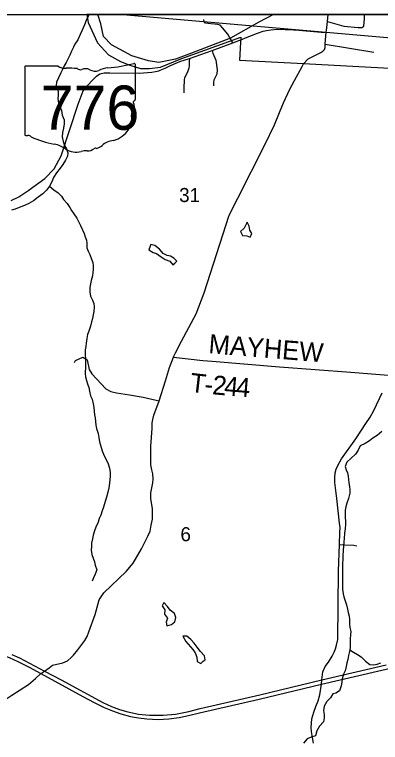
# Model space of a CAD drawing. Extents: x 0 to 34, y 0 to 22.
# Drawn here: x 4.921 to 6.01, y 18.731 to 20.9 of the extents above; entities that cross this region are included whole.
import ezdxf

# ---------------------------------------------------------------- set-up
doc = ezdxf.new("R2010")
doc.units = 0
for name, color, linetype in [('GM_X_City_Street', 7, 'Continuous'), ('GM_X_Corporation', 7, 'Continuous'), ('GM_X_County_Road', 7, 'Continuous'), ('GM_X_Minor_Lake', 7, 'Continuous'), ('GM_X_Minor_River', 7, 'Continuous'), ('GM_X_Rail_Line', 7, 'Continuous'), ('GM_X_Section_Text', 7, 'Continuous'), ('GM_X_State_Location', 7, 'Continuous'), ('GM_X_State_Route', 7, 'Continuous'), ('GM_X_State_Shield', 7, 'Continuous'), ('GM_X_Township_Road', 7, 'Continuous'), ('GM_X_Township_Road_Text', 7, 'Continuous'), ('SH_Data', 7, 'Continuous')]:
    doc.layers.add(name, color=color, linetype=linetype)

msp = doc.modelspace()

# ---------------------------------------------------------------- linework, layer by layer
at = {"layer": 'GM_X_City_Street'}
msp.add_line((5.8464, 20.8121), (5.9912, 20.7882), dxfattribs=at)
for points in [[(5.8528, 20.8797), (5.9019, 20.8656), (5.9446, 20.8613), (5.9548, 20.8618), (5.9608, 20.8657), (5.9629, 20.887), (5.9628, 20.9)], [(5.7819, 20.7534), (5.7957, 20.768), (5.8055, 20.7728), (5.8332, 20.7865), (5.8393, 20.7908), (5.844, 20.7958), (5.8459, 20.8019), (5.8464, 20.8121), (5.8489, 20.8485)]]:
    msp.add_lwpolyline(points, dxfattribs=at)
at = {"layer": 'GM_X_Corporation'}
msp.add_lwpolyline([(7.5423, 20.9), (5.1364, 20.9), (5.1405, 20.8766), (5.1679, 20.8155), (5.2007, 20.7795), (5.2364, 20.7605), (5.2645, 20.749), (5.2964, 20.7394), (5.3232, 20.7393), (5.3551, 20.743), (5.4166, 20.7679), (5.5947, 20.8322), (5.5945, 20.828), (5.5938, 20.8164), (5.5907, 20.7644), (5.7817, 20.7539), (6.0926, 20.7368)], dxfattribs=at)
msp.add_lwpolyline([(6.106, 20.9), (5.2435, 20.9), (6.1004, 20.8259)], close=True, dxfattribs=at)
at = {"layer": 'GM_X_County_Road'}
msp.add_line((5.3944, 19.8788), (5.3957, 19.8816), dxfattribs=at)
for points in [[(5.5856, 20.3524), (5.6666, 20.5116), (5.6951, 20.5713), (5.7096, 20.608), (5.7223, 20.6371), (5.7408, 20.6777), (5.7545, 20.7033), (5.7777, 20.7456), (5.7819, 20.7534)], [(5.3957, 19.8816), (5.4002, 19.8918), (5.4184, 19.9266), (5.4617, 20.0082), (5.4854, 20.0709), (5.5601, 20.3017), (5.5606, 20.3034), (5.5692, 20.32), (5.5856, 20.3524)], [(5.3517, 19.7484), (5.3707, 19.8081), (5.3823, 19.8481), (5.3944, 19.8788)], [(5.0961, 18.9912), (5.1091, 19.0064), (5.1299, 19.0341), (5.1368, 19.046), (5.1423, 19.06), (5.1609, 19.1124), (5.1726, 19.156), (5.1873, 19.1764), (5.2531, 19.2403), (5.2694, 19.259), (5.2739, 19.2654), (5.2988, 19.3072), (5.3181, 19.3452), (5.3245, 19.36), (5.328, 19.3784), (5.3317, 19.396), (5.332, 19.408), (5.332, 19.4279), (5.3272, 19.4563), (5.3263, 19.4743), (5.3325, 19.5045), (5.3333, 19.5161), (5.3323, 19.5308), (5.3301, 19.5435), (5.3269, 19.5579), (5.3272, 19.6132), (5.3304, 19.6663), (5.3311, 19.6829), (5.3328, 19.6935), (5.3359, 19.7063), (5.3517, 19.7484)], [(4.8859, 18.8538), (4.9128, 18.8714), (4.9622, 18.9033), (4.9832, 18.9211), (4.9995, 18.9357), (5.0016, 18.9373), (5.0071, 18.9412), (5.0101, 18.9434), (5.0236, 18.9534), (5.0339, 18.9609), (5.0645, 18.9678), (5.0789, 18.9741), (5.0897, 18.9836), (5.0961, 18.9912)]]:
    msp.add_lwpolyline(points, dxfattribs=at)
at = {"layer": 'GM_X_Minor_Lake'}
for points in [[(5.614, 20.2811), (5.6049, 20.2637), (5.5939, 20.2539), (5.6, 20.2413), (5.6124, 20.2402), (5.623, 20.2364), (5.6254, 20.2424)], [(5.6254, 20.2424), (5.6276, 20.2478), (5.6219, 20.2576), (5.6193, 20.2698), (5.614, 20.2811)], [(5.3215, 20.2022), (5.3207, 20.1988), (5.3339, 20.1912), (5.3438, 20.1882), (5.3577, 20.1779), (5.3698, 20.1696), (5.3835, 20.165), (5.3925, 20.154), (5.3986, 20.1595)], [(5.3986, 20.1595), (5.4043, 20.1646), (5.3956, 20.1741), (5.385, 20.1802), (5.3752, 20.1821), (5.3638, 20.1874), (5.3521, 20.2007), (5.3389, 20.2113), (5.3271, 20.2151), (5.3215, 20.2022)], [(5.3766, 19.1355), (5.3753, 19.137), (5.3655, 19.1477), (5.3602, 19.1378), (5.3681, 19.126), (5.3677, 19.1132), (5.3768, 19.1014), (5.3722, 19.0889), (5.3748, 19.0786), (5.3881, 19.082)], [(5.3881, 19.082), (5.3987, 19.0904), (5.4017, 19.1029), (5.3968, 19.115), (5.3847, 19.1253), (5.3766, 19.1355)], [(5.4217, 19.0475), (5.4312, 19.0312), (5.4516, 19.0076), (5.4587, 18.9974), (5.4633, 18.9845), (5.4644, 18.9716), (5.4753, 18.9663), (5.4829, 18.9725)], [(5.4829, 18.9725), (5.4882, 18.9769), (5.4867, 18.9883), (5.4746, 19.0012), (5.4648, 19.0141), (5.4557, 19.0262), (5.4455, 19.0376), (5.4338, 19.0471), (5.4217, 19.0475)]]:
    msp.add_lwpolyline(points, dxfattribs=at)
at = {"layer": 'GM_X_Minor_River'}
for points in [[(5.1425, 20.9), (5.1401, 20.8954), (5.134, 20.8822), (5.1297, 20.8689), (5.1228, 20.8534), (5.1163, 20.8409), (5.1094, 20.8251), (5.1006, 20.8122), (5.0963, 20.8024), (5.0906, 20.7907), (5.0856, 20.7793), (5.0806, 20.7695), (5.0749, 20.757), (5.0691, 20.7472), (5.0634, 20.7363), (5.0584, 20.726), (5.0515, 20.7117), (5.0457, 20.6981), (5.0445, 20.6886), (5.0486, 20.6787), (5.0504, 20.6692), (5.0507, 20.659), (5.0503, 20.6495), (5.0521, 20.6358), (5.0554, 20.626), (5.061, 20.6142), (5.0632, 20.5997), (5.0688, 20.5864), (5.0687, 20.5743), (5.0667, 20.5614), (5.064, 20.5489), (5.0631, 20.5356), (5.0653, 20.522), (5.0701, 20.5098), (5.0761, 20.4999), (5.0798, 20.4874), (5.0782, 20.4775), (5.0729, 20.4658), (5.0648, 20.453), (5.0572, 20.4424), (5.0461, 20.4284), (5.0373, 20.4148), (5.0323, 20.4012), (5.0247, 20.3888), (5.0163, 20.3771), (5.0056, 20.3661), (4.9915, 20.356), (4.9774, 20.3447), (4.9634, 20.3364), (4.9505, 20.3305), (4.9349, 20.3253), (4.9224, 20.3204), (4.9122, 20.3167)], [(5.0247, 20.3888), (5.0378, 20.3777), (5.0506, 20.3685), (5.0604, 20.3586), (5.0671, 20.3487), (5.0773, 20.3368), (5.0851, 20.3254), (5.0908, 20.3159), (5.0975, 20.3056), (5.1061, 20.2934), (5.1117, 20.2831), (5.1177, 20.271), (5.1278, 20.247), (5.1315, 20.2371), (5.1352, 20.2272), (5.1359, 20.2174), (5.1365, 20.2048), (5.1406, 20.1946), (5.1447, 20.1847), (5.1499, 20.1706), (5.1537, 20.1611), (5.1555, 20.1512), (5.155, 20.1406), (5.1542, 20.1312), (5.1526, 20.1213), (5.1495, 20.1077), (5.1468, 20.0974), (5.1448, 20.0861), (5.1447, 20.074), (5.1469, 20.061), (5.1529, 20.0485), (5.157, 20.0386), (5.1577, 20.0291), (5.1568, 20.0151), (5.1549, 20.0052), (5.1529, 19.9946), (5.1502, 19.984), (5.1474, 19.9715), (5.142, 19.956), (5.1386, 19.9462), (5.1362, 19.9348), (5.1342, 19.9208), (5.133, 19.9102), (5.1314, 19.9007), (5.131, 19.8867), (5.132, 19.873), (5.1323, 19.8617), (5.1319, 19.8507), (5.131, 19.8302), (5.132, 19.8207), (5.1354, 19.8097), (5.1383, 19.7998), (5.1424, 19.788), (5.1442, 19.7778), (5.1472, 19.7633), (5.1516, 19.7538), (5.1553, 19.7394), (5.1571, 19.7284), (5.1582, 19.7181), (5.1593, 19.7071), (5.1607, 19.6976), (5.1618, 19.687), (5.1632, 19.676), (5.1654, 19.6661), (5.1695, 19.6509), (5.1721, 19.6399), (5.1739, 19.6266), (5.1772, 19.6164), (5.182, 19.5996), (5.1883, 19.5848), (5.1936, 19.5742), (5.1995, 19.5612), (5.2036, 19.5483), (5.2061, 19.535), (5.2057, 19.5233), (5.2049, 19.5138), (5.204, 19.5032), (5.2013, 19.4899), (5.1986, 19.477), (5.1951, 19.4615), (5.1908, 19.4483), (5.1861, 19.432), (5.1823, 19.4206), (5.1777, 19.4078), (5.1734, 19.3979), (5.1696, 19.387), (5.163, 19.3718), (5.1588, 19.3612), (5.1549, 19.348), (5.1526, 19.3378), (5.1502, 19.3241), (5.1498, 19.3147), (5.1489, 19.3033), (5.1508, 19.2908), (5.1548, 19.2801), (5.1586, 19.2687), (5.1615, 19.2588), (5.1656, 19.2455), (5.161, 19.2323), (5.1556, 19.2213), (5.1517, 19.2111)], [(6.0149, 19.657), (6.0012, 19.6458), (5.9875, 19.6371), (5.978, 19.63), (5.9651, 19.6217), (5.9499, 19.6146), (5.9445, 19.6021), (5.9361, 19.5901), (5.9235, 19.5776), (5.9109, 19.5663), (5.9052, 19.5531), (5.9085, 19.5436), (5.9126, 19.5337), (5.9144, 19.5238), (5.9151, 19.5143), (5.9162, 19.5045), (5.9184, 19.4931), (5.9195, 19.4832), (5.9198, 19.4734), (5.9155, 19.4575), (5.9109, 19.4438), (5.9078, 19.4329), (5.9058, 19.423), (5.9057, 19.4113), (5.9057, 19.4006), (5.906, 19.3904), (5.9067, 19.3809), (5.9058, 19.3673), (5.9034, 19.354), (5.9026, 19.3388), (5.9018, 19.3282), (5.9005, 19.3157), (5.8993, 19.3028), (5.8984, 19.2869), (5.8988, 19.2774), (5.8979, 19.2626), (5.8975, 19.252), (5.8974, 19.2414), (5.8977, 19.2312), (5.8976, 19.2198), (5.8972, 19.2088), (5.8975, 19.1993), (5.8974, 19.1875), (5.8992, 19.1739), (5.9014, 19.1644), (5.9055, 19.1522), (5.9099, 19.1412), (5.9125, 19.1279), (5.9143, 19.1176), (5.9173, 19.1066), (5.9183, 19.0968), (5.9182, 19.0831), (5.9197, 19.0736), (5.9219, 19.0615), (5.9214, 19.052), (5.9202, 19.0383), (5.92, 19.0125), (5.9181, 19.0016), (5.9157, 18.9894), (5.9134, 18.9777), (5.9106, 18.9675), (5.9087, 18.9573), (5.9052, 18.9436), (5.901, 18.9338), (5.8967, 18.9202), (5.8955, 18.9107), (5.8932, 18.8997), (5.8885, 18.8849), (5.8779, 18.8771), (5.8684, 18.8756), (5.8619, 18.8639), (5.8512, 18.8522), (5.8432, 18.839), (5.8412, 18.8261), (5.8434, 18.8136), (5.8429, 18.8037), (5.8406, 18.792), (5.8288, 18.7792), (5.8215, 18.7652), (5.8172, 18.7508), (5.8043, 18.7467), (5.7926, 18.7415), (5.7815, 18.7283)], [(5.919, 19.0069), (5.9302, 18.9996), (5.9426, 18.9931), (5.9528, 18.9854), (5.9663, 18.9732), (5.9791, 18.9625), (5.9905, 18.962), (6.0011, 18.9642), (6.0117, 18.9676)]]:
    msp.add_lwpolyline(points, dxfattribs=at)
at = {"layer": 'GM_X_Rail_Line'}
msp.add_lwpolyline([(5.6919, 20.9), (5.6482, 20.8769), (5.5644, 20.8293), (5.4477, 20.7849), (5.4, 20.7668), (5.3507, 20.7569), (5.3194, 20.7619), (5.2701, 20.7767), (5.2093, 20.8095), (5.1862, 20.8342), (5.178, 20.872), (5.1687, 20.9)], dxfattribs=at)
at = {"layer": 'GM_X_State_Route'}
msp.add_line((5.8346, 18.9042), (6.0574, 18.9556), dxfattribs=at)
for points in [[(5.8489, 20.8485), (5.8498, 20.8524), (5.8528, 20.8797), (5.8548, 20.9)], [(5.5996, 20.8269), (5.609, 20.8307), (5.6446, 20.8445), (5.6617, 20.8504), (5.671, 20.8526), (5.6839, 20.8548), (5.7048, 20.856), (5.7272, 20.8559), (5.7512, 20.8543), (5.7676, 20.853)], [(5.7676, 20.853), (5.8341, 20.8477), (5.8449, 20.8476), (5.8489, 20.8485)], [(5.442, 20.7688), (5.5099, 20.7929), (5.5713, 20.8156), (5.5996, 20.8269)], [(5.3858, 20.7477), (5.4133, 20.7601), (5.442, 20.7688)], [(4.9646, 20.3775), (5.0113, 20.4115), (5.0388, 20.4405), (5.0602, 20.4793), (5.1106, 20.6333), (5.1255, 20.6727), (5.1329, 20.6825), (5.1501, 20.7012), (5.1652, 20.716), (5.1752, 20.7234), (5.188, 20.7263), (5.2051, 20.726), (5.2917, 20.7258), (5.3296, 20.7286), (5.3409, 20.7304), (5.3511, 20.7327), (5.3545, 20.7341), (5.3693, 20.7403), (5.3858, 20.7477)], [(4.9111, 20.3459), (4.934, 20.3572), (4.963, 20.3763), (4.9646, 20.3775)], [(5.8109, 18.7289), (5.8078, 18.7458), (5.8052, 18.7629), (5.8045, 18.7755), (5.8049, 18.7882), (5.8063, 18.8012), (5.8118, 18.8212), (5.8179, 18.8375), (5.8246, 18.8549), (5.8299, 18.8722), (5.8346, 18.9042), (5.8362, 18.917), (5.8393, 18.9411), (5.8464, 18.9567), (5.8557, 18.9702), (5.8665, 18.9879), (5.8726, 18.9996), (5.8766, 19.0093), (5.8798, 19.0202), (5.8832, 19.0372), (5.8859, 19.2411), (5.8882, 19.3207), (5.8899, 19.3565), (5.8903, 19.3713), (5.8891, 19.3841), (5.8807, 19.4578), (5.875, 19.5049), (5.8743, 19.5191), (5.8756, 19.5337), (5.8791, 19.5454), (5.8837, 19.5564), (5.8949, 19.5758), (5.9368, 19.6355), (5.9672, 19.681), (5.9799, 19.6998), (5.9907, 19.7204), (6.0158, 19.7726)], [(3.9482, 18.6596), (4.0124, 18.69), (4.1263, 18.7432), (4.3074, 18.829), (4.4615, 18.9024), (4.5796, 18.958), (4.6138, 18.9744), (4.6403, 18.9856), (4.6688, 18.9948), (4.701, 19.0034), (4.7301, 19.008), (4.7588, 19.0101), (4.7885, 19.0096), (4.8259, 19.0057), (4.8489, 19.0014), (4.8752, 18.9945), (4.905, 18.9838), (4.9303, 18.9723), (4.964, 18.955), (4.9995, 18.9357)], [(4.9131, 18.9931), (4.9361, 18.983), (4.9955, 18.9512), (5.0101, 18.9434)], [(5.0101, 18.9434), (5.0595, 18.917), (5.184, 18.8496), (5.2095, 18.8381), (5.2334, 18.8289), (5.2587, 18.8217), (5.2901, 18.8148), (5.3227, 18.8116), (5.3635, 18.8116), (5.4002, 18.8151), (5.4398, 18.8228), (5.4738, 18.8315), (5.651, 18.8728), (5.8362, 18.917), (6.0272, 18.9618)], [(4.9995, 18.9357), (5.1245, 18.8679), (5.1581, 18.8499), (5.1883, 18.8346), (5.2123, 18.8247), (5.2378, 18.8159), (5.2659, 18.8081), (5.2897, 18.8037), (5.3144, 18.8007), (5.3488, 18.7992), (5.3807, 18.8011), (5.4113, 18.8052), (5.4393, 18.8108), (5.4722, 18.8187), (5.6493, 18.8599), (5.8346, 18.9042)]]:
    msp.add_lwpolyline(points, dxfattribs=at)
at = {"layer": 'GM_X_State_Shield'}
for p, q in [((4.9511, 20.7427), (4.9511, 20.5426)), ((5.0508, 20.7461), (4.9543, 20.7461)), ((5.2807, 20.6464), (5.2807, 20.7511)), ((5.2806, 20.6464), (5.2807, 20.6464))]:
    msp.add_line(p, q, dxfattribs=at)
for centre, major_axis, start_param, end_param in [((4.9548, 20.7431), (0.00382, 0), 1.712693, 3.28349), ((5.0738, 20.7694), (0.037, 0), 4.042523, 4.731795), ((5.0861, 20.6338), (0.133, 0), 1.404758, 1.657858), ((5.132, 20.721), (0.0222, 0), 0.950623, 2.079405), ((5.2078, 20.685), (0.0703, 0), 1.699011, 2.107814), ((5.1632, 21.019), (0.3495, 0), 4.814394, 5.042369), ((5.277, 20.7515), (0.00367, 0), 6.141152, 7.989035), ((5.1163, 20.7442), (0.0107, 0), 3.836095, 5.185415), ((5.1606, 20.7528), (0.0267, 0), 4.081561, 5.145723), ((5.2798, 20.6387), (0.00568, 0), 1.883978, 3.671073), ((5.2437, 20.6255), (0.0341, 0), 5.934695, 6.695948), ((5.2767, 20.646), (0.00393, 0), 5.05454, 6.418171), ((5.2938, 20.6026), (0.0248, 0), 2.387724, 3.262537), ((5.1828, 20.5893), (0.0874, 0), 5.101752, 6.440018), ((4.9549, 20.5421), (0.00385, 0), 3.00124, 4.508301), ((4.9555, 20.5626), (0.0294, 0), 4.665946, 4.897461), ((4.9615, 20.531), (0.0106, 0), 0.519207, 1.627899), ((5.0953, 20.7108), (0.2524, 0), 4.195997, 4.488961), ((5.2197, 20.4864), (0.0479, 0), 1.647645, 2.488434), ((5.0201, 20.4527), (0.079, 0), 0.823519, 1.323587), ((5.1622, 20.4957), (0.00752, 0), 1.147584, 2.315152), ((5.159, 20.5232), (0.0282, 0), 4.937069, 5.64225), ((5.1055, 20.53), (0.0501, 0), 4.026481, 4.996735), ((5.1344, 20.4609), (0.0412, 0), 1.495662, 1.94098), ((5.1381, 20.5151), (0.0267, 0), 4.691044, 5.507374)]:
    msp.add_ellipse(centre, major_axis=major_axis, ratio=0.8, start_param=start_param, end_param=end_param, dxfattribs=at)
at = {"layer": 'GM_X_Township_Road'}
for points in [[(5.5713, 20.8156), (5.5609, 20.833), (5.5562, 20.842), (5.5403, 20.8607), (5.5334, 20.8679), (5.5266, 20.87), (5.5057, 20.8726), (5.4893, 20.8745), (5.4853, 20.8797), (5.4844, 20.8855)], [(5.5099, 20.7929), (5.5113, 20.7852), (5.5202, 20.7644), (5.5246, 20.7354), (5.5232, 20.7221), (5.5168, 20.7083), (5.5146, 20.7041), (5.513, 20.6989), (5.5134, 20.6875)], [(5.442, 20.7688), (5.4408, 20.7605), (5.441, 20.7485), (5.4403, 20.7406), (5.4383, 20.7339), (5.4341, 20.7244), (5.4274, 20.7117), (5.4256, 20.7055), (5.4254, 20.681), (5.4253, 20.6667)], [(5.0991, 19.8629), (5.1023, 19.8693), (5.1244, 19.8787), (5.137, 19.8707), (5.1433, 19.8424), (5.1511, 19.8296), (5.1931, 19.7844), (5.2076, 19.777), (5.2246, 19.7724), (5.2635, 19.7664), (5.3035, 19.7597), (5.3427, 19.7505), (5.3517, 19.7484)], [(5.3517, 19.7484), (5.3707, 19.8081), (5.3823, 19.8481), (5.3944, 19.8788)], [(5.3944, 19.8788), (5.4816, 19.8694), (5.5092, 19.8667), (5.7096, 19.8503), (5.9222, 19.8343), (6.0338, 19.8257)], [(5.8882, 19.3207), (5.9047, 19.3192), (5.9315, 19.3181), (5.9406, 19.3163)]]:
    msp.add_lwpolyline(points, dxfattribs=at)
at = {"layer": 'SH_Data'}
msp.add_line((2.1, 20.9), (8.9, 20.9), dxfattribs=at)

# ---------------------------------------------------------------- texts
at = {"layer": 'GM_X_Section_Text'}
for s, height, p in [('31', 0.04186, (5.4111, 20.3412)), ('6', 0.0419, (5.4149, 19.3303))]:
    msp.add_text(s, height=height, rotation=0, dxfattribs=at).set_placement(p)
at = {"layer": 'GM_X_State_Location'}
msp.add_text('776', height=0.000189, rotation=0, dxfattribs=at).set_placement((5.0453, 20.6156))
for s, p in [('s', (5.1122, 20.6293)), ('r', (5.1121, 20.6293))]:
    msp.add_text(s, height=0.000189, dxfattribs=at).set_placement(p)
at = {"layer": 'GM_X_State_Shield'}
msp.add_text('776', height=0.13184, dxfattribs=at).set_placement((4.9985, 20.5567))
at = {"layer": 'GM_X_Township_Road_Text'}
for s, height, rotation, p in [('MAYHEW', 0.05682, 355.3966, (5.4973, 19.8909)), ('T', 0.0568, 353.5278, (5.4413, 19.7757)), ('2', 0.0568, 354.8882, (5.5083, 19.7685)), ('4', 0.0568, 355.2698, (5.5435, 19.7653)), ('4', 0.0568, 355.3691, (5.5785, 19.7624)), ('-', 0.0568, 354.465, (5.4846, 19.7708))]:
    msp.add_text(s, height=height, rotation=rotation, dxfattribs=at).set_placement(p)

doc.saveas('drawing.dxf')
